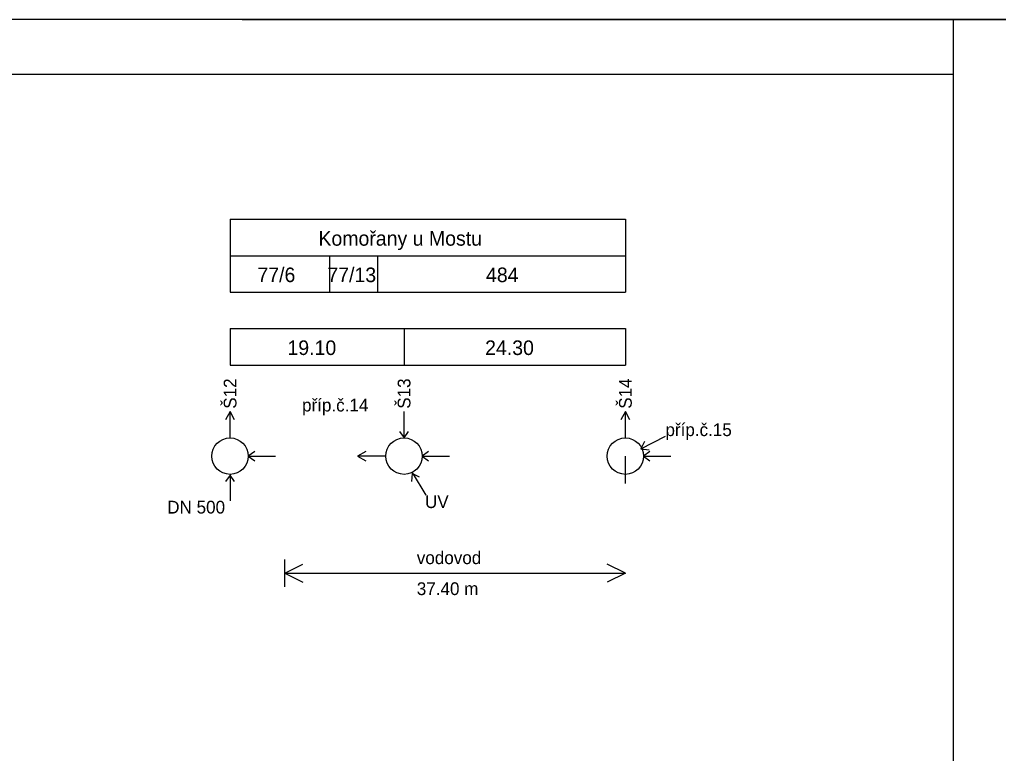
# Model space of a CAD drawing. Extents: x -760612 to 3170, y -975740 to 2995.
# Drawn here: x -394 to 680, y 2189 to 2995 of the extents above; entities that cross this region are included whole.
import ezdxf

# ---------------------------------------------------------------- set-up
doc = ezdxf.new("R2010")
doc.units = 0
for name, color, linetype in [('Border', 7, 'Continuous'), ('Implicitní', 7, 'Continuous'), ('SOUBEH', 7, 'Continuous'), ('Výřez', 7, 'Continuous')]:
    doc.layers.add(name, color=color, linetype=linetype)

# ---------------------------------------------------------------- blocks, each defined once
blk = doc.blocks.new('A3coversheet_v03_CZ_1_1')
at = {"layer": 'Border'}
blk.add_lwpolyline([(0, 0), (4.2, 0), (4.2, 2.97), (0, 2.97)], close=True, dxfattribs=at)
for points in [[(2.1, 0), (2.1, 2.97), (4.2, 2.97)], [(2.1, 0.07), (0.2, 0.07), (0.2, 2.91), (2.1, 2.91)]]:
    blk.add_lwpolyline(points, dxfattribs=at)

msp = doc.modelspace()

# ---------------------------------------------------------------- linework, layer by layer
at = {"layer": 'Implicitní'}
for p, q in [((-150, 2995), (850, 2995)), ((-163.2, 2775.8), (-163.2, 2735.8)), ((-163.2, 2775.8), (270.8, 2775.8)), ((270.8, 2775.8), (270.8, 2735.8)), ((-163.2, 2735.8), (-163.2, 2695.8)), ((-163.2, 2735.8), (-54.2, 2735.8)), ((-163.2, 2735.8), (-54.2, 2735.8)), ((-163.2, 2735.8), (-54.2, 2735.8)), ((-163.2, 2735.8), (270.8, 2735.8)), ((-54.2, 2735.8), (-54.2, 2695.8)), ((-54.2, 2735.8), (-1.2, 2735.8)), ((-54.2, 2735.8), (270.8, 2735.8)), ((-54.2, 2735.8), (270.8, 2735.8)), ((-1.2, 2735.8), (-1.2, 2695.8)), ((-1.2, 2735.8), (270.8, 2735.8)), ((270.8, 2735.8), (270.8, 2695.8)), ((-163.2, 2695.8), (-54.2, 2695.8)), ((-54.2, 2695.8), (-1.2, 2695.8)), ((-1.2, 2695.8), (270.8, 2695.8)), ((-163.2, 2655.8), (-163.2, 2615.8)), ((-163.2, 2655.8), (-163.2, 2655.8)), ((-163.2, 2655.8), (-163.2, 2615.8)), ((-163.2, 2655.8), (27.8, 2655.8)), ((27.8, 2655.8), (27.8, 2615.8)), ((27.8, 2655.8), (270.8, 2655.8)), ((270.8, 2655.8), (270.8, 2615.8)), ((-163.2, 2615.8), (-163.2, 2615.8)), ((-163.2, 2615.8), (27.8, 2615.8)), ((27.8, 2615.8), (270.8, 2615.8)), ((-163.2, 2564.8), (-168.2, 2555.8)), ((-163.2, 2535.8), (-163.2, 2564.8)), ((-158.2, 2555.8), (-163.2, 2564.8)), ((27.8, 2535.8), (27.8, 2564.8)), ((270.8, 2564.8), (265.8, 2555.8)), ((270.8, 2535.8), (270.8, 2564.8)), ((275.8, 2555.8), (270.8, 2564.8)), ((22.8, 2542.8), (27.8, 2535.8)), ((27.8, 2535.8), (32.8, 2542.8)), ((287.8, 2523.8), (314.8, 2537.8)), ((291.8, 2531.8), (287.8, 2523.8)), ((-136.2, 2520.8), (-143.2, 2515.8)), ((-143.2, 2515.8), (-113.2, 2515.8)), ((-143.2, 2515.8), (-136.2, 2510.8)), ((-14.2, 2520.8), (-23.2, 2515.8)), ((-23.2, 2515.8), (-14.2, 2510.8)), ((7.8, 2515.8), (-22.2, 2515.8)), ((54.8, 2520.8), (47.8, 2515.8)), ((47.8, 2515.8), (77.8, 2515.8)), ((47.8, 2515.8), (54.8, 2510.8)), ((287.8, 2523.8), (296.8, 2522.8)), ((297.8, 2520.8), (290.8, 2515.8)), ((290.8, 2515.8), (320.8, 2515.8)), ((290.8, 2515.8), (297.8, 2510.8)), ((-163.2, 2494.8), (-168.2, 2487.8)), ((-163.2, 2495.8), (-163.2, 2466.8)), ((-158.2, 2487.8), (-163.2, 2494.8)), ((36.8, 2496.8), (35.8, 2487.8)), ((36.8, 2497.8), (51.8, 2472.8)), ((44.8, 2492.8), (36.8, 2496.8))]:
    msp.add_line(p, q, dxfattribs=at)
for centre in [(-163.2, 2515.8), (27.8, 2515.8), (270.8, 2515.8)]:
    msp.add_circle(centre, 20, dxfattribs=at)
at = {"layer": 'SOUBEH'}
for p, q in [((270.8, 2485.8), (270.8, 2515.8)), ((-103.2, 2372.3), (-103.2, 2402.3)), ((-103.2, 2387.3), (-83.2, 2397.3)), ((270.8, 2387.3), (250.8, 2397.3)), ((-103.2, 2387.3), (270.8, 2387.3)), ((-103.2, 2387.3), (-83.2, 2377.3)), ((270.8, 2387.3), (250.8, 2377.3))]:
    msp.add_line(p, q, dxfattribs=at)
at = {"layer": 'Výřez'}
msp.add_lwpolyline([(-1469, 25), (2731, 25), (2731, 2995), (-1469, 2995)], close=True, dxfattribs=at)

# ---------------------------------------------------------------- block references
at = {"layer": 'Border', "xscale": 1000.0000004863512, "yscale": 1000.0000004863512, "rotation": 4.518606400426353e-10}
msp.add_blockref('A3coversheet_v03_CZ_1_1', (-1469, 25), dxfattribs=at)

# ---------------------------------------------------------------- texts
at = {"layer": 'Implicitní'}
for s, height, p in [('Komořany u Mostu', 16, (-66.2, 2746.8)), ('77/6', 16, (-133.2, 2706.8)), ('77/13', 16, (-56.4, 2706.8)), ('484', 16, (117.8, 2706.8)), ('19.10', 16, (-100.2, 2626.8)), ('24.30', 16, (116.8, 2626.8)), ('příp.č.14', 14, (-84.2, 2564.8)), ('příp.č.15', 14, (314.8, 2537.8)), ('UV', 14, (50.8, 2458.8)), ('DN 500', 14, (-232.2, 2452.8))]:
    msp.add_text(s, height=height, dxfattribs=at).set_placement(p)
for s, p in [('Š12', (-156.2, 2567.8)), ('Š13', (34.8, 2567.8)), ('Š14', (277.8, 2567.8))]:
    msp.add_text(s, height=14, rotation=90, dxfattribs=at).set_placement(p)
at = {"layer": 'SOUBEH'}
for s, p in [('vodovod', (41.8, 2397.3)), ('37.40 m', (41.8, 2363.3))]:
    msp.add_text(s, height=14, dxfattribs=at).set_placement(p)

doc.saveas('drawing.dxf')
